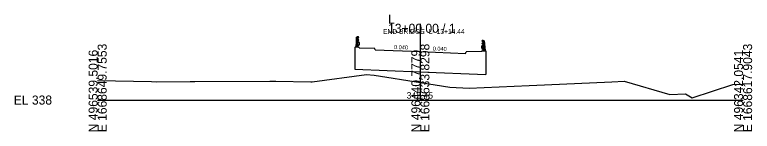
# Model space of a CAD drawing. Extents: x -26 to 203, y -10 to 5517.
# Drawn here: x -25.7 to 202.8, y 2990.3 to 3026.5 of the extents above; entities that cross this region are included whole.
import ezdxf

# ---------------------------------------------------------------- set-up
doc = ezdxf.new("R2010")
doc.units = 0
for name, color, linetype in [('Exist Cross Section Cell', 7, 'Continuous'), ('Exist XS Center Line Elevation Label', 7, 'Continuous'), ('Exist XS Ground Line', 7, 'Continuous'), ('Prop XS Bridge', 7, 'Continuous'), ('Prop XS SE Text', 7, 'Continuous'), ('Prop XSC Text', 7, 'Continuous')]:
    doc.layers.add(name, color=color, linetype=linetype)

msp = doc.modelspace()

# ---------------------------------------------------------------- linework, layer by layer
at = {"layer": 'Exist Cross Section Cell'}
for p, q in [((100, 3000), (100, 3023.69)), ((0, 3000), (100, 3000)), ((100, 3000), (200, 3000))]:
    msp.add_line(p, q, dxfattribs=at)
at = {"layer": 'Exist XS Ground Line'}
for p, q in [((66.43, 3005.65), (83.34, 3007.9)), ((83.34, 3007.9), (85.67, 3007.77)), ((85.67, 3007.77), (100, 3005.45)), ((0, 3006.12), (16.7, 3005.74)), ((16.7, 3005.74), (18.19, 3005.69)), ((18.19, 3005.69), (28.66, 3005.77)), ((28.66, 3005.77), (30.11, 3005.73)), ((30.11, 3005.73), (53.36, 3005.9)), ((53.36, 3005.9), (55.22, 3005.85)), ((55.22, 3005.85), (66.06, 3005.66)), ((66.06, 3005.66), (66.43, 3005.65)), ((100, 3005.45), (109.16, 3003.97)), ((138.51, 3004.73), (159.28, 3005.68)), ((159.28, 3005.68), (163.19, 3005.84)), ((163.19, 3005.84), (177.31, 3001.75)), ((109.16, 3003.97), (115.09, 3003.69)), ((115.09, 3003.69), (133.7, 3004.53)), ((133.7, 3004.53), (138.51, 3004.73)), ((184.21, 3000.66), (196.8, 3004.8)), ((196.8, 3004.8), (200, 3004.91)), ((177.31, 3001.75), (182.17, 3001.91)), ((182.17, 3001.91), (184.21, 3000.66))]:
    msp.add_line(p, q, dxfattribs=at)
at = {"layer": 'Prop XS Bridge'}
for p, q in [((80.58, 3017.75), (80.85, 3017.98)), ((80.58, 3017.26), (80.85, 3017.03)), ((80.99, 3017.91), (80.99, 3017.1)), ((119.02, 3016.7), (119.01, 3016.79)), ((119.42, 3016.63), (119.15, 3016.86)), ((79.71, 3016.36), (79.77, 3016.42)), ((79.71, 3016.36), (79.71, 3009.59)), ((80.93, 3016.42), (79.77, 3016.42)), ((80.05, 3016.41), (79.99, 3016.41)), ((80.74, 3016.41), (80.66, 3016.41)), ((81, 3016.35), (80.93, 3016.42)), ((81, 3016.17), (81, 3016.35)), ((81, 3016.17), (85.83, 3016.09)), ((86, 3015.59), (85.83, 3016.09)), ((86, 3015.59), (100, 3015.03)), ((100, 3015.03), (114, 3014.47)), ((114, 3014.47), (114.17, 3014.97)), ((119, 3015.05), (114.17, 3014.97)), ((119, 3015.23), (119.07, 3015.3)), ((119, 3015.05), (119, 3015.23)), ((119.01, 3016.42), (119.01, 3016.38)), ((119.01, 3016.34), (119.01, 3016.38)), ((119.02, 3016.06), (119.01, 3015.98)), ((119.07, 3015.3), (120.23, 3015.3)), ((119.42, 3016.14), (119.15, 3015.91)), ((119.26, 3015.29), (119.34, 3015.29)), ((119.95, 3015.29), (120.01, 3015.29)), ((120.29, 3015.24), (120.23, 3015.3)), ((120.29, 3015.24), (120.29, 3007.96)), ((79.71, 3009.59), (99.75, 3008.78)), ((99.75, 3008.78), (120.29, 3007.96))]:
    msp.add_line(p, q, dxfattribs=at)
for points in [[(80.57, 3019.64), (80.42, 3019.64), (80.22, 3019.55), (80.2, 3019.55), (79.95, 3016.52), (79.95, 3016.49), (80.57, 3016.49), (80.57, 3019.64), (80.42, 3019.64), (80.42, 3016.49), (80.22, 3016.49), (80.22, 3019.55)], [(119.43, 3018.52), (119.58, 3018.52), (119.78, 3018.43), (119.8, 3018.43), (120.05, 3015.4), (120.05, 3015.37), (119.43, 3015.37), (119.43, 3018.52), (119.58, 3018.52), (119.58, 3015.37), (119.78, 3015.37), (119.78, 3018.43)]]:
    msp.add_lwpolyline(points, dxfattribs=at)
for centre, radius, start, end in [((80.91, 3017.92), 0.0824, 353.9328, 129.4432), ((80.91, 3017.09), 0.0824, 230.5568, 6.0672), ((119.09, 3016.8), 0.0824, 50.5568, 186.0672), ((118.79, 3016.67), 0.23, 349.2013, 6.82), ((119.26, 3016.6), 0.247, 173.18, 190.7949), ((118.75, 3016.51), 0.279, 341.4179, 354.5265), ((118.75, 3016.25), 0.279, 5.4735, 18.5821), ((119.09, 3015.97), 0.0824, 173.9328, 309.4432), ((118.8, 3016.51), 0.23, 353.18, 10.7987), ((118.8, 3016.25), 0.23, 349.2013, 6.82), ((119.26, 3016.16), 0.247, 169.2051, 186.82), ((118.79, 3016.09), 0.23, 353.18, 10.7987)]:
    msp.add_arc(centre, radius, start, end, dxfattribs=at)
for centre, major_axis, start_param, end_param in [((80.57, 3019.47), (0.392, 0), 0, 1.570796), ((80.57, 3019.47), (0.392, 0), 4.712389, 6.283185), ((80.57, 3018.65), (0.392, 0), 0, 1.570796), ((80.57, 3018.65), (0.392, 0), 4.712389, 6.283185), ((119.43, 3018.35), (-0.392, 0), 4.712389, 6.283185), ((119.43, 3018.35), (-0.392, 0), 0, 1.570796), ((119.43, 3017.53), (-0.392, 0), 4.712389, 6.283185), ((119.43, 3017.53), (-0.392, 0), 0, 1.570796)]:
    msp.add_ellipse(centre, major_axis=major_axis, ratio=0.42124, start_param=start_param, end_param=end_param, dxfattribs=at)

# ---------------------------------------------------------------- texts
at = {"layer": 'Exist Cross Section Cell'}
for s, p in [('L', (90, 3023.69)), ('13+00.00 / 1', (90, 3020.89)), ('EL 338', (-26, 2998.6))]:
    msp.add_text(s, height=2.8, dxfattribs=at).set_placement(p)
for s, p in [('E 1668649.7553', (2.8, 2990)), ('E 1668633.8298', (102.8, 2990)), ('E 1668617.9043', (202.8, 2990)), ('N 496539.5016', (0, 2990)), ('N 496440.7779', (100, 2990)), ('N 496342.0541', (200, 2990))]:
    msp.add_text(s, height=2.8, rotation=90, dxfattribs=at).set_placement(p)
at = {"layer": 'Exist XS Center Line Elevation Label'}
msp.add_text('343.45', height=2, dxfattribs=at).set_placement((95.74, 3000.45))
at = {"layer": 'Prop XS SE Text'}
for p in [(91.81, 3015.86), (103.81, 3015.38)]:
    msp.add_text('0.040', height=1.25, rotation=357.7094, dxfattribs=at).set_placement(p)
at = {"layer": 'Prop XSC Text'}
msp.add_text('END BRIDGE -L- 13+14.44', height=1.5, dxfattribs=at).set_placement((88.45, 3020.53))

doc.saveas('drawing.dxf')
